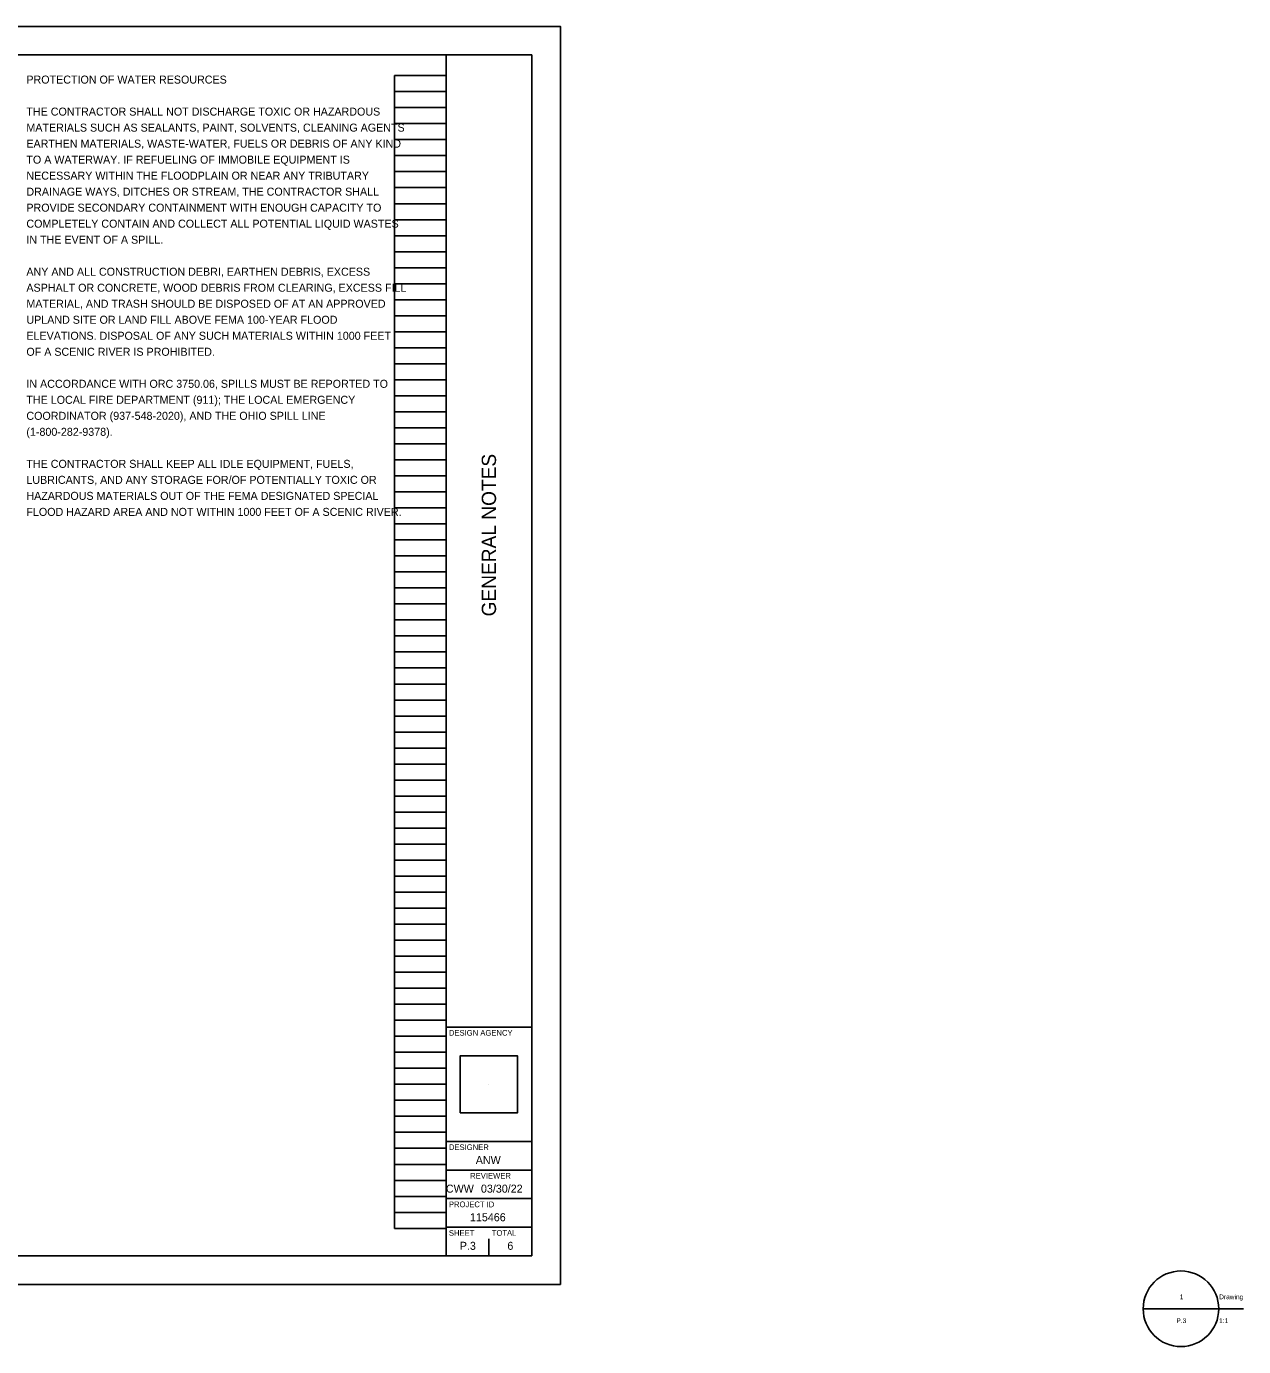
# Model space of a CAD drawing. Extents: x 0 to 46, y -1.1 to 22.
# Drawn here: x 24.66 to 45.95, y -1.09 to 22 of the extents above; entities that cross this region are included whole.
import ezdxf

# ---------------------------------------------------------------- set-up
doc = ezdxf.new("R2010")
doc.units = 0
for name, color, linetype in [('Default', 7, 'Continuous'), ('SH_Border', 7, 'Continuous'), ('SH_Cut_Line', 7, 'Continuous'), ('SH_Data', 7, 'Continuous'), ('SH_Text', 7, 'Continuous')]:
    doc.layers.add(name, color=color, linetype=linetype)

msp = doc.modelspace()

# ---------------------------------------------------------------- linework, layer by layer
at = {"layer": 'Default'}
for p, q in [((44.194, -0.426), (45.517, -0.426)), ((44.861, -0.426), (45.951, -0.426))]:
    msp.add_line(p, q, dxfattribs=at)
msp.add_circle((44.855, -0.426), 0.661, dxfattribs=at)
at = {"layer": 'SH_Border'}
for p, q in [((32, 0.5), (32, 21.5)), ((32, 4.5), (33.5, 4.5)), ((32, 2.5), (33.5, 2.5)), ((32, 2), (33.5, 2)), ((32, 1.5), (33.5, 1.5)), ((32, 1), (33.5, 1))]:
    msp.add_line(p, q, dxfattribs=at)
msp.add_lwpolyline([(1.5, 21.5), (33.5, 21.5), (33.5, 0.5), (1.5, 0.5)], close=True, dxfattribs=at)
at = {"layer": 'SH_Cut_Line'}
msp.add_lwpolyline([(0, 0), (34, 0), (34, 22), (0, 22)], close=True, dxfattribs=at)
at = {"layer": 'SH_Data'}
for p, q in [((31.1, 0.98), (31.1, 21.14)), ((31.1, 21.14), (32, 21.14)), ((32, 0.98), (32, 21.14)), ((31.1, 20.86), (32, 20.86)), ((31.1, 20.58), (32, 20.58)), ((31.1, 20.3), (32, 20.3)), ((31.1, 20.02), (32, 20.02)), ((31.1, 19.74), (32, 19.74)), ((31.1, 19.46), (32, 19.46)), ((31.1, 19.18), (32, 19.18)), ((31.1, 18.9), (32, 18.9)), ((31.1, 18.62), (32, 18.62)), ((31.1, 18.34), (32, 18.34)), ((31.1, 18.06), (32, 18.06)), ((31.1, 17.78), (32, 17.78)), ((31.1, 17.5), (32, 17.5)), ((31.1, 17.22), (32, 17.22)), ((31.1, 16.94), (32, 16.94)), ((31.1, 16.66), (32, 16.66)), ((31.1, 16.38), (32, 16.38)), ((31.1, 16.1), (32, 16.1)), ((31.1, 15.82), (32, 15.82)), ((31.1, 15.54), (32, 15.54)), ((31.1, 15.26), (32, 15.26)), ((31.1, 14.98), (32, 14.98)), ((31.1, 14.7), (32, 14.7)), ((31.1, 14.42), (32, 14.42)), ((31.1, 14.14), (32, 14.14)), ((31.1, 13.86), (32, 13.86)), ((31.1, 13.58), (32, 13.58)), ((31.1, 13.3), (32, 13.3)), ((31.1, 13.02), (32, 13.02)), ((31.1, 12.74), (32, 12.74)), ((31.1, 12.46), (32, 12.46)), ((31.1, 12.18), (32, 12.18)), ((31.1, 11.9), (32, 11.9)), ((31.1, 11.62), (32, 11.62)), ((31.1, 11.34), (32, 11.34)), ((31.1, 11.06), (32, 11.06)), ((31.1, 10.78), (32, 10.78)), ((31.1, 10.5), (32, 10.5)), ((31.1, 10.22), (32, 10.22)), ((31.1, 9.94), (32, 9.94)), ((31.1, 9.66), (32, 9.66)), ((31.1, 9.38), (32, 9.38)), ((31.1, 9.1), (32, 9.1)), ((31.1, 8.82), (32, 8.82)), ((31.1, 8.54), (32, 8.54)), ((31.1, 8.26), (32, 8.26)), ((31.1, 7.98), (32, 7.98)), ((31.1, 7.7), (32, 7.7)), ((31.1, 7.42), (32, 7.42)), ((31.1, 7.14), (32, 7.14)), ((31.1, 6.86), (32, 6.86)), ((31.1, 6.58), (32, 6.58)), ((31.1, 6.3), (32, 6.3)), ((31.1, 6.02), (32, 6.02)), ((31.1, 5.74), (32, 5.74)), ((31.1, 5.46), (32, 5.46)), ((31.1, 5.18), (32, 5.18)), ((31.1, 4.9), (32, 4.9)), ((31.1, 4.62), (32, 4.62)), ((31.1, 4.34), (32, 4.34)), ((31.1, 4.06), (32, 4.06)), ((31.1, 3.78), (32, 3.78)), ((31.1, 3.5), (32, 3.5)), ((32.75, 3.5), (32.75, 3.5)), ((31.1, 3.22), (32, 3.22)), ((31.1, 2.94), (32, 2.94)), ((31.1, 2.66), (32, 2.66)), ((31.1, 2.38), (32, 2.38)), ((31.1, 2.1), (32, 2.1)), ((31.1, 1.82), (32, 1.82)), ((31.1, 1.54), (32, 1.54)), ((31.1, 1.26), (32, 1.26)), ((31.1, 0.98), (32, 0.98)), ((32.75, 0.5), (32.75, 0.8)), ((32.375, 0.675), (32.375, 0.675))]:
    msp.add_line(p, q, dxfattribs=at)
msp.add_lwpolyline([(32.25, 3), (33.25, 3), (33.25, 4), (32.25, 4)], close=True, dxfattribs=at)

# ---------------------------------------------------------------- texts
at = {"layer": 'Default'}
for s, p in [('1', (44.834, -0.259)), ('Drawing', (45.523, -0.259)), ('P.3', (44.776, -0.676)), ('1:1', (45.523, -0.676))]:
    msp.add_text(s, height=0.0833, dxfattribs=at).set_placement(p)
at = {"layer": 'SH_Data'}
msp.add_text('GENERAL NOTES', height=0.25, rotation=90, dxfattribs=at).set_placement((32.875, 11.682))
for s, height, p in [('DESIGN AGENCY', 0.1, (32.05, 4.35)), ('DESIGNER', 0.1, (32.05, 2.35)), ('ANW', 0.14, (32.52, 2.105)), ('REVIEWER', 0.1, (32.422, 1.85)), ('CWW', 0.14, (31.998, 1.605)), ('03/30/22', 0.14, (32.611, 1.605)), ('PROJECT ID', 0.1, (32.05, 1.35)), ('115466', 0.14, (32.419, 1.105)), ('SHEET', 0.1, (32.05, 0.85)), ('TOTAL', 0.1, (32.8, 0.85)), ('P.3', 0.14, (32.241, 0.605)), ('6', 0.14, (33.073, 0.605))]:
    msp.add_text(s, height=height, dxfattribs=at).set_placement(p)
at = {"layer": 'SH_Text'}
for s, p in [('PROTECTION OF WATER RESOURCES', (24.66, 21)), ('THE CONTRACTOR SHALL NOT DISCHARGE TOXIC OR HAZARDOUS', (24.66, 20.44)), ('MATERIALS SUCH AS SEALANTS, PAINT, SOLVENTS, CLEANING AGENTS', (24.66, 20.16)), ('EARTHEN MATERIALS, WASTE-WATER, FUELS OR DEBRIS OF ANY KIND', (24.66, 19.88)), ('TO A WATERWAY. IF REFUELING OF IMMOBILE EQUIPMENT IS ', (24.66, 19.6)), ('NECESSARY WITHIN THE FLOODPLAIN OR NEAR ANY TRIBUTARY ', (24.66, 19.32)), ('DRAINAGE WAYS, DITCHES OR STREAM, THE CONTRACTOR SHALL ', (24.66, 19.04)), ('PROVIDE SECONDARY CONTAINMENT WITH ENOUGH CAPACITY TO ', (24.66, 18.76)), ('COMPLETELY CONTAIN AND COLLECT ALL POTENTIAL LIQUID WASTES ', (24.66, 18.48)), ('IN THE EVENT OF A SPILL. ', (24.66, 18.2)), ('ANY AND ALL CONSTRUCTION DEBRI, EARTHEN DEBRIS, EXCESS ', (24.66, 17.64)), ('ASPHALT OR CONCRETE, WOOD DEBRIS FROM CLEARING, EXCESS FILL ', (24.66, 17.36)), ('MATERIAL, AND TRASH SHOULD BE DISPOSED OF AT AN APPROVED ', (24.66, 17.08)), ('UPLAND SITE OR LAND FILL ABOVE FEMA 100-YEAR FLOOD ', (24.66, 16.8)), ('ELEVATIONS. DISPOSAL OF ANY SUCH MATERIALS WITHIN 1000 FEET ', (24.66, 16.52)), ('OF A SCENIC RIVER IS PROHIBITED.', (24.66, 16.24)), ('IN ACCORDANCE WITH ORC 3750.06, SPILLS MUST BE REPORTED TO ', (24.66, 15.68)), ('THE LOCAL FIRE DEPARTMENT (911); THE LOCAL EMERGENCY ', (24.66, 15.4)), ('COORDINATOR (937-548-2020), AND THE OHIO SPILL LINE ', (24.66, 15.12)), ('(1-800-282-9378).', (24.66, 14.84)), ('THE CONTRACTOR SHALL KEEP ALL IDLE EQUIPMENT, FUELS, ', (24.66, 14.28)), ('LUBRICANTS, AND ANY STORAGE FOR/OF POTENTIALLY TOXIC OR ', (24.66, 14)), ('HAZARDOUS MATERIALS OUT OF THE FEMA DESIGNATED SPECIAL ', (24.66, 13.72)), ('FLOOD HAZARD AREA AND NOT WITHIN 1000 FEET OF A SCENIC RIVER.', (24.66, 13.44))]:
    msp.add_text(s, height=0.14, dxfattribs=at).set_placement(p)

doc.saveas('drawing.dxf')
